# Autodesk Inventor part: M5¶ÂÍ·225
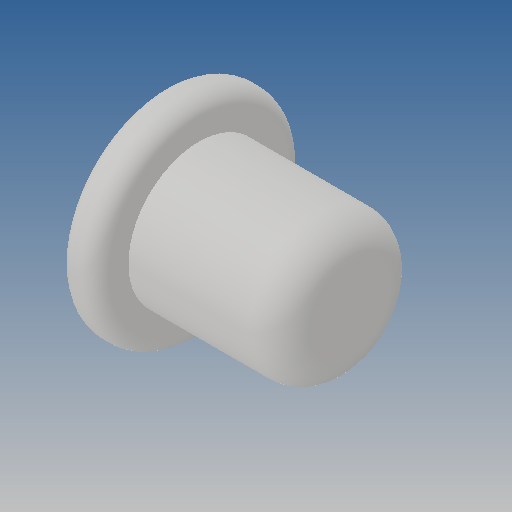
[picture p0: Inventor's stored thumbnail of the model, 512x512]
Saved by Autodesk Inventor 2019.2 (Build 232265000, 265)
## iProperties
Created: 2013-07
Part Number: M5¶ÂÍ·225
Material: Ogólny
Document SubType Name: Modeling
Designer: CADENGINEERING4
Density: 1 g/cm^3
Appearance: Domyślna
Author: CADENGINEERING4
Revision Number: ÈÎºÎ
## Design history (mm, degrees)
feature "Ðý×ª1"
node "Bryła1"
